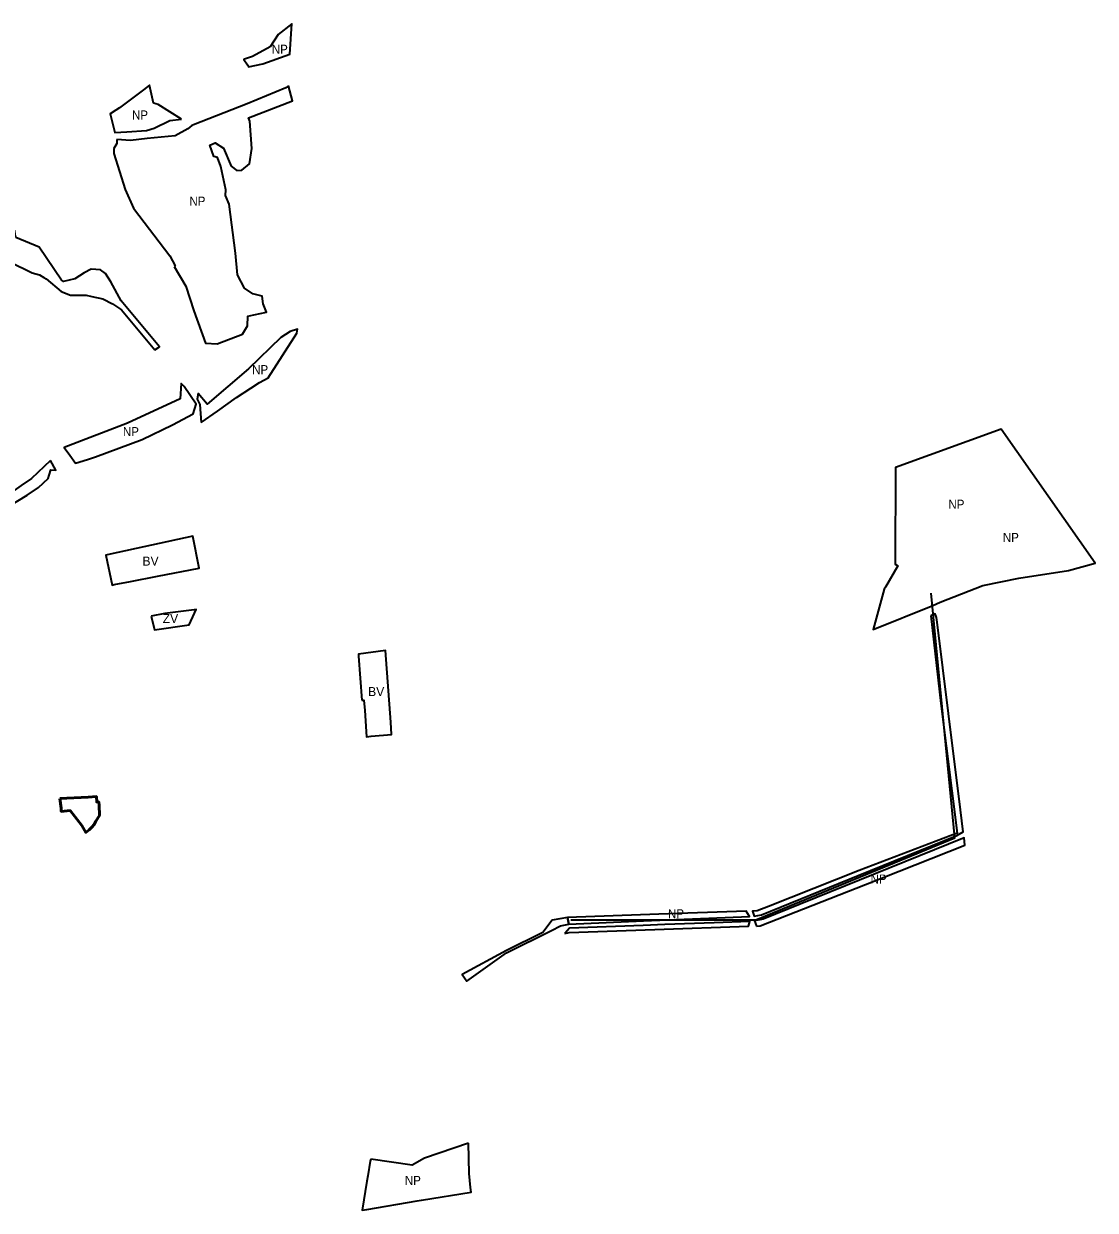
# Model space of a CAD drawing. Extents: x -650276 to -642489, y -1074311 to -1066720.
# Drawn here: x -643906 to -642489, y -1070593 to -1069023 of the extents above; entities that cross this region are included whole.
import ezdxf

# ---------------------------------------------------------------- set-up
doc = ezdxf.new("R2010")
doc.units = 0
doc.header["$LTSCALE"] = 4.8
for name, color, linetype, lineweight in [('3', 7, 'Continuous', 35), ('40', 7, 'Continuous', 35), ('48', 7, 'Continuous', 35), ('54', 7, 'Continuous', 35), ('60', 7, 'Continuous', 53)]:
    doc.layers.add(name, color=color, linetype=linetype, lineweight=lineweight)
doc.layers.add('62', color=7, linetype='Continuous')

msp = doc.modelspace()

# ---------------------------------------------------------------- linework, layer by layer
at = {"layer": '3'}
for points in [[(-643791.88, -1069725.25), (-643797.75, -1069726.51), (-643789.3, -1069766.05), (-643786.35, -1069765.46), (-643764.94, -1069761.27), (-643729.34, -1069754.3), (-643674.3, -1069743.53), (-643682.61, -1069701.16)], [(-643459.13, -1069918.47), (-643456.14, -1069918.26), (-643455.15, -1069931.99), (-643452.63, -1069967.09), (-643446.63, -1069966), (-643419.62, -1069963.66), (-643420.79, -1069947.35), (-643427.6, -1069852.59), (-643463.51, -1069857.44), (-643463.31, -1069860.18)]]:
    msp.add_lwpolyline(points, close=True, dxfattribs=at)
at = {"layer": '40'}
msp.add_lwpolyline([(-643737.47, -1069807.24), (-643733.02, -1069825.4), (-643687.2, -1069818.8), (-643680.15, -1069803.22), (-643678.02, -1069798.52), (-643680.83, -1069798.86), (-643719.42, -1069803.49)], close=True, dxfattribs=at)
at = {"layer": '48'}
for points in [[(-643589.94, -1069076.36), (-643554.17, -1069063.59), (-643551.72, -1069023.19), (-643569.44, -1069037.24), (-643580.21, -1069053.96), (-643603.72, -1069066.5), (-643614.36, -1069070.29), (-643614.82, -1069070.45), (-643610.31, -1069077.52), (-643608.65, -1069080.11)], [(-643671.53, -1069551.1), (-643649.94, -1069535.93), (-643624.65, -1069517.85), (-643605.97, -1069505.47), (-643594.49, -1069498.17), (-643582.77, -1069491.76), (-643545.07, -1069432.89), (-643544.06, -1069427.6), (-643553.7, -1069430.44), (-643565.92, -1069438.4), (-643608.89, -1069479.72), (-643663.46, -1069526.87), (-643675.32, -1069512.62), (-643676.9, -1069519.91), (-643673.34, -1069527.08)], [(-643845.304, -1069594.087), (-643837.72, -1069604.62), (-643822.06, -1069600.07), (-643811.16, -1069596.45), (-643749.64, -1069573.35), (-643709.33, -1069554.14), (-643682.27, -1069539.41), (-643678.24, -1069526.44), (-643693.95, -1069503.38), (-643697.85, -1069499.21), (-643699.23, -1069519.48), (-643769.08, -1069551.96), (-643852.51, -1069584.08)], [(-642589.86, -1069757.1), (-642524.14, -1069746.8), (-642488.71, -1069736.85), (-642613.34, -1069559.68), (-642753.18, -1069610.65), (-642753.25, -1069738.59), (-642750.08, -1069740.57), (-642766.27, -1069769), (-642767.89, -1069771.42), (-642782.69, -1069824.93), (-642703.57, -1069792.88), (-642693.99, -1069788.85), (-642637.44, -1069766.81)], [(-643870.697, -1069601.241), (-643895.951, -1069625.069), (-643909.616, -1069634.267), (-643926.229, -1069646.367), (-643992.34, -1069677.76), (-643994.36, -1069701.05), (-643982.84, -1069695.93), (-643977.582, -1069692.76), (-643901.55, -1069646.92), (-643886.62, -1069636.87), (-643873.82, -1069625.05), (-643872.55, -1069620.75), (-643870.44, -1069613.56), (-643863.92, -1069613.9)], [(-642706.3, -1069806.69), (-642693.2, -1069922.89), (-642671.23, -1070094.16), (-642801.19, -1070143.75), (-642921.03, -1070191.32), (-642936.02, -1070197.23), (-642942.12, -1070197.4), (-642940.12, -1070204.42), (-642930.02, -1070202.54), (-642802.38, -1070150.51), (-642671.9, -1070097.32), (-642663.28, -1070092.67), (-642667.19, -1070063.71), (-642682.78, -1069935.98), (-642697.64, -1069815.14), (-642698.77, -1069809.17), (-642700.34, -1069804.12), (-642701.17, -1069804.49)], [(-642936.88, -1070217.27), (-642931.88, -1070217.1), (-642792.87, -1070162.36), (-642661.13, -1070110.48), (-642662.32, -1070100.64), (-642879.2, -1070188.43), (-642928.07, -1070208.21), (-642939.51, -1070210.35)], [(-643185.16, -1070214.62), (-643187.06, -1070205.98), (-643207.1, -1070209.72), (-643219.4, -1070225.8), (-643267.55, -1070249.49), (-643326.26, -1070281.43), (-643320, -1070290.2), (-643267.75, -1070252.77), (-643208.09, -1070223.14), (-643196.16, -1070217.22)], [(-643190.42, -1070226.99), (-643184.86, -1070225.91), (-643071.16, -1070221.95), (-642947.42, -1070217.64), (-642945.59, -1070211.49), (-642992.64, -1070213.18), (-643058.07, -1070215.38), (-643086.58, -1070216.57), (-643184.22, -1070220.08)], [(-643066.26, -1070201.69), (-643187.06, -1070205.98), (-643185.16, -1070214.62), (-643086.36, -1070210.57), (-642946.24, -1070204.83), (-642950.42, -1070197.58)]]:
    msp.add_lwpolyline(points, close=True, dxfattribs=at)
for points in [[(-643697.29, -1069149.7), (-643728.49, -1069129.95), (-643734.75, -1069128.3), (-643739.66, -1069104.58), (-643747.75, -1069110.71), (-643779.31, -1069134.63), (-643784.55, -1069137.77), (-643792.04, -1069142.27), (-643785.6, -1069166.98), (-643769.71, -1069166.04)], [(-643555.98, -1069105.57), (-643559.5, -1069107.98), (-643610.81, -1069129.04), (-643681.63, -1069157.04), (-643683.68, -1069157.86), (-643688.91, -1069162.16), (-643705.7, -1069171.37), (-643743.11, -1069175.08), (-643764.86, -1069177.58), (-643782.92, -1069176.24)], [(-643607.02, -1069152.34), (-643609.08, -1069147.64), (-643550.79, -1069125.24), (-643555.98, -1069105.57)], [(-643769.71, -1069166.04), (-643743.99, -1069164.43), (-643733.83, -1069161.46), (-643712.74, -1069151.46), (-643697.29, -1069149.7)], [(-643707.23, -1069344.52), (-643691.6, -1069370.3), (-643681.09, -1069403.24), (-643665.87, -1069446.1), (-643650.28, -1069446.91), (-643616.78, -1069433.81), (-643610.18, -1069422.91), (-643609.6, -1069409.99), (-643601.9, -1069408.43), (-643585.19, -1069404.76), (-643589.52, -1069393.88), (-643590.89, -1069383.9), (-643602.92, -1069380.53), (-643614.35, -1069373.28), (-643623.28, -1069355.47), (-643625.9, -1069326.77), (-643634.56, -1069262.02), (-643639.23, -1069250.38), (-643638.72, -1069242.94), (-643645.61, -1069212.25), (-643649.84, -1069200.4), (-643654.57, -1069198.77), (-643660.22, -1069184.11), (-643653.05, -1069180.98), (-643641.84, -1069187.68), (-643631.66, -1069211.67), (-643624.38, -1069217.27), (-643617.64, -1069217), (-643607.37, -1069208.43), (-643604.38, -1069188.48), (-643607.02, -1069152.34)], [(-643782.92, -1069176.24), (-643783.2, -1069181.85), (-643786.97, -1069188.11), (-643786.89, -1069195.02), (-643771.86, -1069242.77), (-643761.21, -1069267.12), (-643712.78, -1069330.24)], [(-643732.705, -1069454.79), (-643726.74, -1069450.72), (-643777.27, -1069389.71), (-643791.02, -1069364.54), (-643798.1, -1069353.51), (-643804.83, -1069348.99), (-643817.06, -1069348.14), (-643826.21, -1069352.92), (-643838.69, -1069360.79), (-643853.56, -1069364.44), (-643856.43, -1069362.68), (-643885.63, -1069318.72), (-643916.78, -1069305.89), (-643917.36, -1069302.04), (-643918.08, -1069297.33), (-643926.74, -1069287.37), (-643944.89, -1069278.32), (-643946.16, -1069281.84), (-644015.12, -1069254.24)], [(-644054.35, -1069303.55), (-644035.89, -1069301.02), (-644025.24, -1069301.38), (-644014.19, -1069303.36), (-643993.91, -1069309.57), (-643936.87, -1069332.93), (-643924.42, -1069338.29), (-643894.84, -1069352.76), (-643885.22, -1069355.58), (-643879.48, -1069359.13), (-643876.34, -1069360.61), (-643856.58, -1069377.59), (-643844.28, -1069382.26), (-643823.72, -1069382.61), (-643815.93, -1069384.23), (-643801.36, -1069387.23), (-643788.63, -1069393.7), (-643776.78, -1069401.87), (-643732.705, -1069454.79)], [(-643712.78, -1069330.24), (-643705.74, -1069343.54), (-643707.23, -1069344.52)], [(-643452.22, -1070592.35), (-643385.72, -1070580.86), (-643380.35, -1070580.14), (-643380.08, -1070580.09), (-643314.51, -1070569.69), (-643315.27, -1070563.2), (-643317.08, -1070544.75), (-643317.9, -1070504.73)], [(-643317.9, -1070504.73), (-643376.07, -1070524.59), (-643392.41, -1070533.68), (-643446.89, -1070526.01)], [(-643446.89, -1070526.01), (-643447.79, -1070528.63), (-643450.98, -1070547.74), (-643452.14, -1070554.77)], [(-643452.14, -1070554.77), (-643458.42, -1070593.43), (-643452.22, -1070592.35)]]:
    msp.add_lwpolyline(points, dxfattribs=at)
at = {"layer": '54'}
msp.add_lwpolyline([(-643182.326, -1070209.281), (-642937.896, -1070209.281), (-642674.665, -1070100.645), (-642706.002, -1069776.828)], dxfattribs=at)
at = {"layer": '60'}
msp.add_lwpolyline([(-643858.23, -1070048.35), (-643856.72, -1070061.26), (-643856.49, -1070065.66), (-643844.87, -1070064.51), (-643829.38, -1070084.37), (-643824.22, -1070093.34), (-643819.67, -1070089.82), (-643815.9, -1070086.27), (-643813.21, -1070082.8), (-643810.91, -1070078.63), (-643806.17, -1070071.18), (-643806.59, -1070057.37), (-643806.86, -1070053.03), (-643809.71, -1070053.15), (-643810, -1070046), (-643820.78, -1070046.59)], close=True, dxfattribs=at)

# ---------------------------------------------------------------- texts
at = {"layer": '62', "width": 0.95}
for p in [(-643577.985, -1069062.967), (-643762.985, -1069149.967), (-643686.985, -1069263.967), (-643603.985, -1069486.967), (-643774.985, -1069568.967), (-642682.928, -1069665.096), (-642610.928, -1069709.096), (-642785.928, -1070161.096), (-643053.928, -1070207.096), (-643401.985, -1070559.967)]:
    msp.add_text('NP', height=12, dxfattribs=at).set_placement(p)
at = {"layer": '62'}
for s, p in [('BV', (-643749.135, -1069740.303)), ('ZV', (-643722.385, -1069816.315)), ('BV', (-643450.639, -1069913.037))]:
    msp.add_text(s, height=12, dxfattribs=at).set_placement(p)

doc.saveas('drawing.dxf')
